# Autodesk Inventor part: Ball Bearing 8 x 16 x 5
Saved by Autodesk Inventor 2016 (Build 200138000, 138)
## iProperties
Created: 2015-11
Part Number: Ball Bearing 8 x 16 x 5
Material: Generic
Document SubType Name: Modeling
Designer: John
Density: 1 g/cm^3
Appearance: Default
Author: John
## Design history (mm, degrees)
feature "SOLID1"
body "Solid1"
